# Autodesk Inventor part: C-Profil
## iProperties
Created: 2005-12
Part Number: C-Profil
Document SubType Name: Modeling
Designer: Sascha
Manufacturer: Standard
Standards Organization: Custom
Author: Sascha
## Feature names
1. Extrusion1
2. Rundung1 [Fillet]
3. Rundung2 [Fillet]
4. Extrusion2
